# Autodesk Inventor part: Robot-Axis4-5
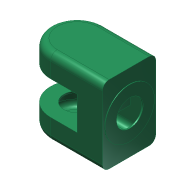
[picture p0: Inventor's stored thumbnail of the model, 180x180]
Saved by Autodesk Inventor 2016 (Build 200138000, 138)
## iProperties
Shininess: 21.0
Length Units: 11269
Angle Units: 11279
Time Units: 11290
Mass Units: 11283
Length Display Precision: 3
Angle Display Precision: 2
Created: 2001-08
Part Number: Robot-Axis4-5
Document SubType Name: ﾓﾃﾞﾘﾝｸﾞ
Designer: Administrator
Density: 1 g/cm^3
Material: Generic
Mass: 112.04 g
Surface Area: 1128.11 cm^2
Volume: 112.04 cm^3
Appearance: Sea Green
Density: 0.0
Volumn: 0.0
Area: 0.0
PropertySet Name: Model Information
Control State: 0
Master: False
Checked Out: False
Author: Administrator
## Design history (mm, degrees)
sketch "ｽｹｯﾁ1"
  geometry: L1 (0, -40)-(-118, -40); L2 (-118, -40)-(-118, 40); L3 (-118, 40)-(0, 40); L4 (0, 40)-(0, -40); L5 (-118, 0)-(0, 0); L6 (-78, 40)-(-78, -40); 2 further points
  constraints: 12 end point, 4 point on line, 3 midpoint, 2 horizontal, 2 parallel, 1 perpendicular, 1 vertical, 1 vertical alignment, 3 other
  dimensions: "d0" = 80 distance of L1.end L2.end; "d1" = 118 distance of L2.end L3.end
extrude "押し出し1" new body sketch "ｽｹｯﾁ1" stored distance "d2" = 116; taper "d3" = 0 deg
node "作業平面1"
sketch "ｽｹｯﾁ2"
  geometry: L1 (0, 40)-(-78, 40) reference; L2 (-78, -40)-(0, -40) reference; L3 (-38, 40)-(-38, -40); C1 r 40 at (-78, 0); A1 r 40 centre (-78, 0) between (-78, 40) and (-78, -40) reference
  constraints: 2 end point, 2 point on line, 1 centre point, 1 coincident, 1 concentric, 1 perpendicular, 1 tangent
extrude "押し出し2" cut sketch "ｽｹｯﾁ2" stored distance "d4" = 50; taper "d5" = 0 deg
sketch "ｽｹｯﾁ3"
  geometry: L1 (0, 0)-(0, 60) reference; L2 (-116, 60)-(-116, 0) reference; L3 (-116, 30)-(0, 30); L4 (-33, 70)-(-83, 70) reference; L5 (-58, 70)-(-58, -10); L6 (-83, -10)-(-33, -10) reference; C1 r 37 at (-58, 30)
  constraints: 5 midpoint, 4 end point, 1 centre point
  dimensions: "d7" = 74 diameter of C1
extrude "押し出し3" join sketch "ｽｹｯﾁ3" distance "d8" = 1; taper "d9" = 0 deg
node "作業軸1"
shell "Shell1" dims "d10" = 2
sketch "Sketch4"
  geometry: C1 r 37 at (0, 0) reference
hole "Hole1" sketch "Sketch4" at (0, 0) diameter "d11" = 40; stored, may be unused: countersink angle "d15" = 82 deg, drill point angle "d17" = 118 deg; dims "d12" = 6, "d13" = 4, "d14" = 2, "d16" = 2
sketch "Sketch5"
  geometry: A1 r 40 centre (-78, 0) between (-78, 40) and (-78, -40) reference
hole "Hole2" sketch "Sketch5" at (-78, 0) diameter "d18" = 40; stored, may be unused: countersink angle "d22" = 82 deg, drill point angle "d24" = 118 deg; dims "d19" = 6, "d20" = 4, "d21" = 2, "d23" = 2
sketch "Sketch6"
  geometry: A1 r 40 centre (78, 0) between (78, -40) and (78, 40) reference
hole "Hole3" sketch "Sketch6" at (78, 0) diameter "d25" = 40; stored, may be unused: countersink angle "d29" = 82 deg, drill point angle "d31" = 118 deg; dims "d26" = 6, "d27" = 4, "d28" = 2, "d30" = 2
body "Solid1"
fillet "Fillet1" dims "d6" = 10
